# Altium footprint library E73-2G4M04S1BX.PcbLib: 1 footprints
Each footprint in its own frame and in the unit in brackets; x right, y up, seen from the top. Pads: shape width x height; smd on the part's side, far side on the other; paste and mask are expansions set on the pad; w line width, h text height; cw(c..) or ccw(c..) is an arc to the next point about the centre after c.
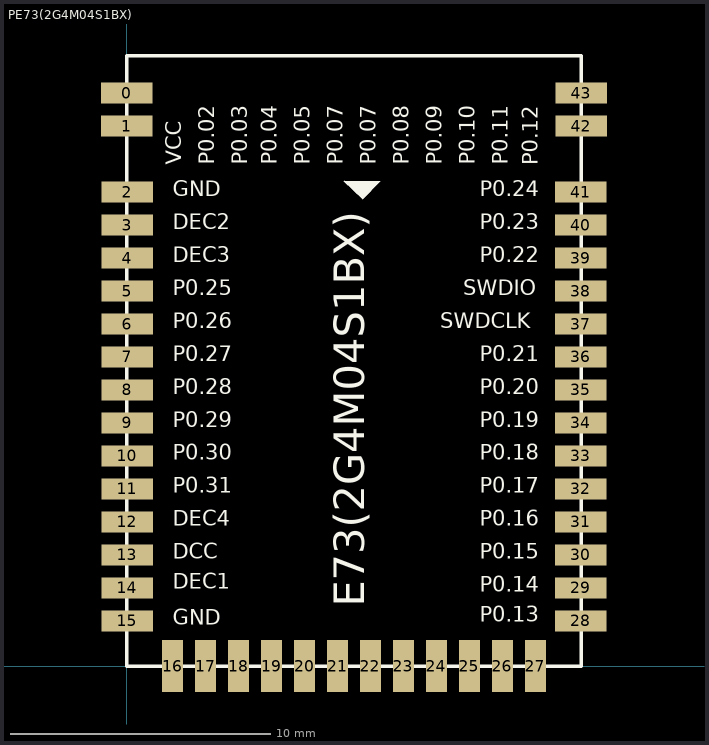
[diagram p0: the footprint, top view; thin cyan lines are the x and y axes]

## PE73(2G4M04S1BX) [mm] "28.7mm*17.5mm*2.60mm-S"
pads (44):
  rect 2x0.8 smd: 0(0,22.065) 1(0,20.795) 2(0.02,18.255) 3(0.02,16.985) 4(0.02,15.715) 5(0.02,14.445) 6(0.02,13.175) 7(0.02,11.905) 8(0.02,10.635) 9(0.02,9.365) 10(0.02,8.095) 11(0.02,6.825) 12(0.02,5.555) 13(0.02,4.285) 14(0.02,3.015) 15(0.02,1.745) 28(17.48,1.745) 29(17.48,3.015) 30(17.48,4.285) 31(17.48,5.555) 32(17.48,6.825) 33(17.48,8.095) 34(17.48,9.365) 35(17.48,10.635) 36(17.48,11.905) 37(17.48,13.175) 38(17.48,14.445) 39(17.48,15.715) 40(17.48,16.985) 41(17.48,18.255) 42(17.5,20.795) 43(17.5,22.065)
  rect 0.8x2 smd: 16(1.765,0) 17(3.035,0) 18(4.305,0) 19(5.575,0) 20(6.845,0) 21(8.115,0) 22(9.385,0) 23(10.655,0) 24(11.925,0) 25(13.195,0) 26(14.465,0) 27(15.735,0)
Top Overlay:
  region: 8.37,18.69 9.76,18.68 9.08,17.98 8.36,18.68
  lines w0.127: 0,23.5 0,0 17.5,0 17.5,23.5 ; 0.011,23.498 17.478,23.498
  text "P0.12" at 16.009,19.295 h1
  text "P0.11" at 14.859,19.304 h1
  text "P0.10" at 13.589,19.304 h1
  text "P0.09" at 12.319,19.304 h1
  text "P0.08" at 11.049,19.304 h1
  text "P0.07" at 9.779,19.304 h1
  text "P0.07" at 8.509,19.304 h1
  text "P0.05" at 7.239,19.304 h1
  text "P0.04" at 5.969,19.304 h1
  text "P0.03" at 4.826,19.304 h1
  text "P0.02" at 3.556,19.304 h1
  text "VCC" at 2.286,19.304 h1
  text "P0.24" at 13.589,17.907 h1
  text "P0.23" at 13.589,16.637 h1
  text "P0.22" at 13.589,15.367 h1
  text "SWDIO" at 12.954,14.097 h1
  text "SWDCLK" at 12.065,12.827 h1
  text "P0.21" at 13.589,11.557 h1
  text "P0.20" at 13.589,10.287 h1
  text "P0.19" at 13.589,9.017 h1
  text "P0.18" at 13.589,7.747 h1
  text "P0.17" at 13.589,6.477 h1
  text "P0.16" at 13.589,5.207 h1
  text "P0.15" at 13.589,3.937 h1
  text "P0.14" at 13.589,2.667 h1
  text "P0.13" at 13.589,1.524 h1
  text "GND" at 1.778,1.397 h1
  text "DEC1" at 1.778,2.794 h1
  text "DCC" at 1.778,3.937 h1
  text "DEC4" at 1.778,5.207 h1
  text "P0.31" at 1.778,6.477 h1
  text "P0.30" at 1.778,7.747 h1
  text "P0.29" at 1.778,9.017 h1
  text "P0.28" at 1.778,10.287 h1
  text "P0.27" at 1.778,11.557 h1
  text "P0.26" at 1.778,12.827 h1
  text "P0.25" at 1.778,14.097 h1
  text "DEC3" at 1.778,15.367 h1
  text "DEC2" at 1.778,16.637 h1
  text "GND" at 1.778,17.907 h1
  text "E73(2G4M04S1BX)" at 9.525,2.286 h2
